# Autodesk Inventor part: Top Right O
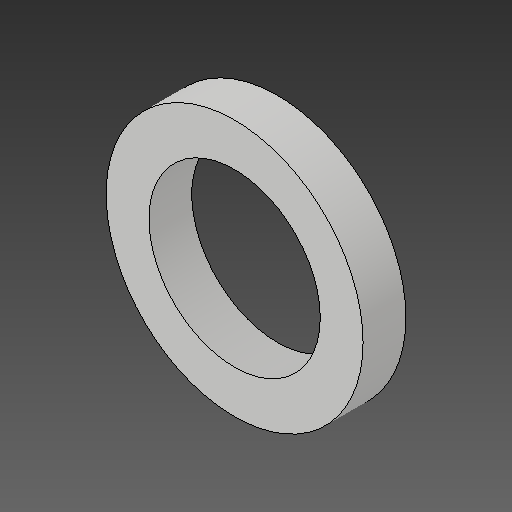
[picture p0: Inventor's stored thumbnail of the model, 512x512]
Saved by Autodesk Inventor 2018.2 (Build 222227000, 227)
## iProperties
Created: 2018-03
Part Number: Top Right O
Material: Generic
Document SubType Name: Modeling
Designer: PeterMaxwell-Stewart
Mass: 1.9635 g
Surface Area: 15.708 cm^2
Volume: 1.9635 cm^3
Density: 1 g/cm^3
Appearance: Default
Author: PeterMaxwell-Stewart
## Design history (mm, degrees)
derived "O's and X's.ipt"
feature "Top Right O::O's and X's.ipt" dims "d0" = 10
tag "TaggingFeature1"
body "Solid1"
